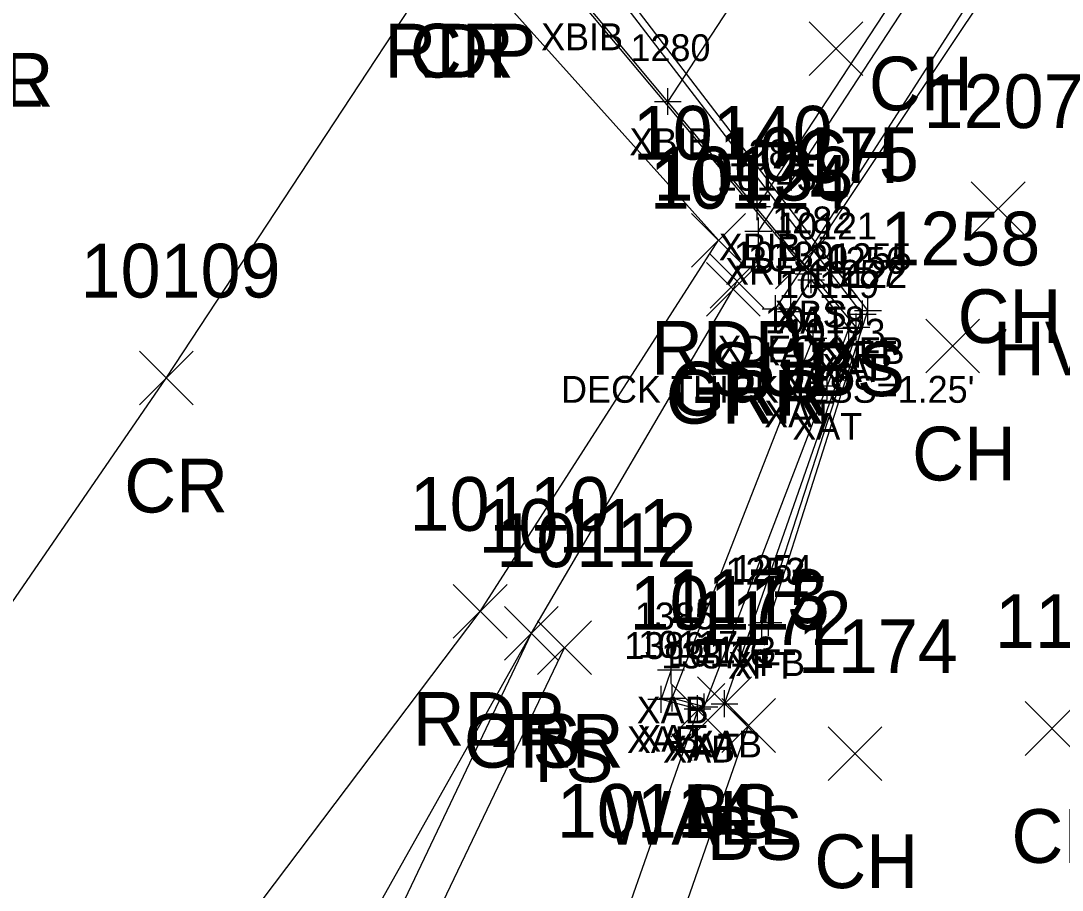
# Model space of a CAD drawing. Extents: x 1651685 to 1653558, y 889533 to 891085.
# Drawn here: x 1652681.1 to 1652719.83, y 890214.62 to 890246.97 of the extents above; entities that cross this region are included whole.
import ezdxf

# ---------------------------------------------------------------- set-up
doc = ezdxf.new("R2010")
doc.units = 0
for name, color, linetype in [('B_A', 7, 'Continuous'), ('B_C', 7, 'Continuous'), ('B_I', 7, 'Continuous'), ('B_TIC', 7, 'Continuous'), ('BB', 7, 'Continuous'), ('BELB', 7, 'Continuous'), ('BFT', 7, 'Continuous'), ('BR', 7, 'Continuous'), ('BSE', 7, 'Continuous'), ('BSUBM', 7, 'Continuous'), ('C_A', 7, 'Continuous'), ('L_A', 7, 'Continuous'), ('L_I', 7, 'Continuous'), ('L_TIC', 7, 'Continuous'), ('LELB', 7, 'Continuous'), ('LW', 7, 'Continuous'), ('P_A', 7, 'Continuous'), ('P_I', 7, 'Continuous'), ('P_TIC', 7, 'Continuous'), ('PET', 7, 'Continuous'), ('PRC', 7, 'Continuous'), ('R_A', 7, 'Continuous'), ('R_I', 7, 'Continuous'), ('R_TIC', 7, 'Continuous'), ('RGR', 7, 'Continuous'), ('U_A', 7, 'Continuous'), ('U_I', 7, 'Continuous'), ('U_TIC', 7, 'Continuous'), ('USA', 7, 'Continuous')]:
    doc.layers.add(name, color=color, linetype=linetype)

msp = doc.modelspace()

# ---------------------------------------------------------------- linework, layer by layer
at = {"layer": 'B_TIC'}
for p, q in [((1652705.17, 890243.967), (1652705.246, 890243.967)), ((1652708.492, 890240.052), (1652708.568, 890240.052)), ((1652708.538, 890239.146), (1652708.614, 890239.146)), ((1652710.404, 890237.557), (1652710.479, 890237.557)), ((1652710.5, 890237.331), (1652710.575, 890237.331)), ((1652709.175, 890236.253), (1652709.251, 890236.253)), ((1652709.747, 890236.148), (1652709.822, 890236.148)), ((1652712.414, 890236.055), (1652712.49, 890236.055)), ((1652712.613, 890236.191), (1652712.689, 890236.191)), ((1652712.179, 890235.573), (1652712.255, 890235.573)), ((1652710.58, 890235.155), (1652710.656, 890235.155)), ((1652711.907, 890235.524), (1652711.982, 890235.524)), ((1652710.049, 890233.837), (1652710.125, 890233.837)), ((1652711.096, 890233.378), (1652711.172, 890233.378)), ((1652711.096, 890233.378), (1652711.172, 890233.378)), ((1652708.661, 890224.484), (1652708.737, 890224.484)), ((1652708.916, 890224.583), (1652708.991, 890224.583)), ((1652705.29, 890222.819), (1652705.365, 890222.819)), ((1652704.926, 890221.718), (1652705.001, 890221.718)), ((1652705.33, 890221.765), (1652705.405, 890221.765)), ((1652706.273, 890221.367), (1652706.348, 890221.367)), ((1652706.527, 890221.439), (1652706.602, 890221.439)), ((1652706.527, 890221.439), (1652706.602, 890221.439)), ((1652707.276, 890221.555), (1652707.352, 890221.555))]:
    msp.add_line(p, q, dxfattribs=at)
for points in [[(1652705.167, 890243.467), (1652705.167, 890244.467)], [(1652704.667, 890243.967), (1652705.667, 890243.967)], [(1652708.489, 890239.552), (1652708.489, 890240.552)], [(1652707.989, 890240.052), (1652708.989, 890240.052)], [(1652708.535, 890238.646), (1652708.535, 890239.646)], [(1652708.035, 890239.146), (1652709.035, 890239.146)], [(1652710.4, 890237.057), (1652710.4, 890238.057)], [(1652709.9, 890237.557), (1652710.9, 890237.557)], [(1652710.496, 890236.831), (1652710.496, 890237.831)], [(1652709.996, 890237.331), (1652710.996, 890237.331)], [(1652709.172, 890235.753), (1652709.172, 890236.753)], [(1652709.743, 890235.648), (1652709.743, 890236.648)], [(1652712.411, 890235.555), (1652712.411, 890236.555)], [(1652712.61, 890235.691), (1652712.61, 890236.691)], [(1652708.672, 890236.253), (1652709.672, 890236.253)], [(1652709.243, 890236.148), (1652710.243, 890236.148)], [(1652711.903, 890235.024), (1652711.903, 890236.024)], [(1652711.911, 890236.055), (1652712.911, 890236.055)], [(1652712.11, 890236.191), (1652713.11, 890236.191)], [(1652712.176, 890235.073), (1652712.176, 890236.073)], [(1652710.577, 890234.655), (1652710.577, 890235.655)], [(1652711.676, 890235.573), (1652712.676, 890235.573)], [(1652710.077, 890235.155), (1652711.077, 890235.155)], [(1652711.403, 890235.524), (1652712.403, 890235.524)], [(1652710.046, 890233.337), (1652710.046, 890234.337)], [(1652709.546, 890233.837), (1652710.546, 890233.837)], [(1652711.093, 890232.878), (1652711.093, 890233.878)], [(1652711.093, 890232.878), (1652711.093, 890233.878)], [(1652710.593, 890233.378), (1652711.593, 890233.378)], [(1652710.593, 890233.378), (1652711.593, 890233.378)], [(1652708.912, 890224.083), (1652708.912, 890225.083)], [(1652708.658, 890223.984), (1652708.658, 890224.984)], [(1652708.158, 890224.484), (1652709.158, 890224.484)], [(1652708.412, 890224.583), (1652709.412, 890224.583)], [(1652705.286, 890222.319), (1652705.286, 890223.319)], [(1652704.786, 890222.819), (1652705.786, 890222.819)], [(1652704.922, 890221.218), (1652704.922, 890222.218)], [(1652705.326, 890221.265), (1652705.326, 890222.265)], [(1652707.273, 890221.055), (1652707.273, 890222.055)], [(1652704.422, 890221.718), (1652705.422, 890221.718)], [(1652704.826, 890221.765), (1652705.826, 890221.765)], [(1652706.269, 890220.867), (1652706.269, 890221.867)], [(1652706.523, 890220.939), (1652706.523, 890221.939)], [(1652706.523, 890220.939), (1652706.523, 890221.939)], [(1652705.769, 890221.367), (1652706.769, 890221.367)], [(1652706.023, 890221.439), (1652707.023, 890221.439)], [(1652706.023, 890221.439), (1652707.023, 890221.439)], [(1652706.773, 890221.555), (1652707.773, 890221.555)]]:
    msp.add_lwpolyline(points, dxfattribs=at)
at = {"layer": 'BB'}
for points in [[(1652718.204, 890263.952), (1652705.167, 890243.967)], [(1652721.557, 890259.987), (1652708.489, 890240.052)]]:
    msp.add_lwpolyline(points, dxfattribs=at)
at = {"layer": 'BELB'}
msp.add_lwpolyline([(1652709.172, 890236.253), (1652723.445, 890257.661), (1652723.976, 890257.346), (1652725.092, 890258.712), (1652723.412, 890260.555)], dxfattribs=at)
at = {"layer": 'BFT'}
for points in [[(1652708.912, 890224.583), (1652712.61, 890236.191), (1652701.636, 890250.529), (1652698.138, 890254.709), (1652696.627, 890256.861)], [(1652708.658, 890224.484), (1652712.411, 890236.055), (1652701.467, 890250.302), (1652696.763, 890256.497), (1652694.576, 890256.579)]]:
    msp.add_lwpolyline(points, dxfattribs=at)
at = {"layer": 'BR'}
msp.add_lwpolyline([(1652708.535, 890239.146), (1652722.284, 890260.183)], dxfattribs=at)
at = {"layer": 'BSE'}
msp.add_lwpolyline([(1652688.419, 890263.77), (1652698.151, 890252.192), (1652698.185, 890252.136), (1652710.4, 890237.557)], dxfattribs=at)
at = {"layer": 'BSUBM'}
for points in [[(1652707.273, 890221.555), (1652712.176, 890235.573), (1652700.432, 890249.63), (1652694.576, 890256.579), (1652684.615, 890268.453), (1652678.722, 890266.546)], [(1652706.523, 890221.439), (1652705.326, 890221.765), (1652710.046, 890233.837), (1652710.577, 890235.155), (1652709.743, 890236.148), (1652710.496, 890237.331), (1652711.903, 890235.524), (1652711.093, 890233.378)], [(1652706.523, 890221.439), (1652711.093, 890233.378)], [(1652705.286, 890222.819), (1652704.922, 890221.718), (1652706.269, 890221.367)]]:
    msp.add_lwpolyline(points, dxfattribs=at)
at = {"layer": 'L_TIC'}
for points in [[(1652710.419, 890244.933), (1652712.419, 890246.933)], [(1652712.419, 890244.933), (1652710.419, 890246.933)], [(1652716.454, 890238.976), (1652718.454, 890240.976)], [(1652718.454, 890238.976), (1652716.454, 890240.976)], [(1652714.763, 890233.863), (1652716.763, 890235.863)], [(1652716.763, 890233.863), (1652714.763, 890235.863)], [(1652699.091, 890223.174), (1652701.091, 890225.174)], [(1652701.091, 890223.174), (1652699.091, 890225.174)], [(1652700.322, 890222.637), (1652702.322, 890224.637)], [(1652702.322, 890222.637), (1652700.322, 890224.637)], [(1652706.273, 890220.555), (1652708.273, 890222.555)], [(1652708.273, 890220.555), (1652706.273, 890222.555)], [(1652705.281, 890220.305), (1652707.281, 890222.305)], [(1652707.281, 890220.305), (1652705.281, 890222.305)], [(1652707.172, 890219.743), (1652709.172, 890221.743)], [(1652709.172, 890219.743), (1652707.172, 890221.743)], [(1652718.459, 890219.631), (1652720.459, 890221.631)], [(1652720.459, 890219.631), (1652718.459, 890221.631)], [(1652711.128, 890218.692), (1652713.128, 890220.692)], [(1652713.128, 890218.692), (1652711.128, 890220.692)]]:
    msp.add_lwpolyline(points, dxfattribs=at)
at = {"layer": 'LELB'}
for points in [[(1652059.958, 889769.148), (1652077.097, 889776.338), (1652118.687, 889793.555), (1652148.832, 889805.136), (1652195.565, 889824.702), (1652235.22, 889839.021), (1652273.168, 889851.707), (1652312.186, 889868.505), (1652346.463, 889887.35), (1652384.438, 889904.888), (1652418.627, 889927.641), (1652449.257, 889948.785), (1652484.179, 889973.177), (1652505.899, 889994.659), (1652536.895, 890025.511), (1652566.282, 890055.689), (1652594.629, 890083.579), (1652622.175, 890122.044), (1652650.057, 890154.468), (1652669.869, 890181.835), (1652676.091, 890189.411), (1652687.771, 890202.227), (1652700.091, 890224.174)], [(1652693.386, 890207.032), (1652701.322, 890223.637)], [(1652711.469, 890174.982), (1652709.134, 890184.396), (1652705.235, 890200.05), (1652703.806, 890206.099), (1652704.13, 890209.141), (1652708.172, 890220.743), (1652707.273, 890221.555)]]:
    msp.add_lwpolyline(points, dxfattribs=at)
at = {"layer": 'LW'}
msp.add_lwpolyline([(1652703.573, 890213.567), (1652706.281, 890221.305)], dxfattribs=at)
at = {"layer": 'P_TIC'}
for points in [[(1652706.052, 890237.801), (1652708.052, 890239.801)], [(1652708.052, 890237.801), (1652706.052, 890239.801)], [(1652685.512, 890232.671), (1652687.512, 890234.671)], [(1652687.512, 890232.671), (1652685.512, 890234.671)], [(1652697.186, 890223.989), (1652699.186, 890225.989)], [(1652699.186, 890223.989), (1652697.186, 890225.989)]]:
    msp.add_lwpolyline(points, dxfattribs=at)
at = {"layer": 'PET'}
msp.add_lwpolyline([(1652310.071, 889873.858), (1652345.018, 889890.876), (1652381.133, 889910.269), (1652416.225, 889931.732), (1652447.247, 889952.285), (1652474.07, 889972.993), (1652503.702, 889997.944), (1652534.457, 890027.787), (1652563.385, 890057.924), (1652590.108, 890087.923), (1652620.326, 890123.876), (1652646.593, 890156.843), (1652667.225, 890184.01), (1652673.844, 890192.76), (1652698.186, 890224.989), (1652707.052, 890238.801), (1652697.139, 890249.857), (1652688.173, 890260.372)], dxfattribs=at)
at = {"layer": 'PRC'}
msp.add_lwpolyline([(1652339.131, 889902.361), (1652374.757, 889921.453), (1652409.696, 889942.759), (1652439.668, 889962.958), (1652466.375, 889983.158), (1652495.638, 890007.899), (1652525.652, 890036.364), (1652554.01, 890065.879), (1652580.922, 890096.263), (1652611.449, 890132.238), (1652636.96, 890165.085), (1652656.957, 890191.595), (1652665.106, 890202.523), (1652686.512, 890233.671), (1652697.139, 890249.857)], dxfattribs=at)
at = {"layer": 'R_TIC'}
for points in [[(1652706.742, 890236.28), (1652708.742, 890238.28)], [(1652708.742, 890236.28), (1652706.742, 890238.28)], [(1652706.601, 890235.977), (1652708.601, 890237.977)], [(1652708.601, 890235.977), (1652706.601, 890237.977)], [(1652699.091, 890223.174), (1652701.091, 890225.174)], [(1652701.091, 890223.174), (1652699.091, 890225.174)]]:
    msp.add_lwpolyline(points, dxfattribs=at)
at = {"layer": 'RGR'}
msp.add_lwpolyline([(1652681.549, 890185.195), (1652688.877, 890200.577), (1652700.091, 890224.174), (1652707.601, 890236.977), (1652707.742, 890237.28)], dxfattribs=at)
at = {"layer": 'U_TIC'}
for points in [[(1652709.168, 890237), (1652711.168, 890239)], [(1652711.168, 890237), (1652709.168, 890239)]]:
    msp.add_lwpolyline(points, dxfattribs=at)
at = {"layer": 'USA'}
msp.add_lwpolyline([(1652723.048, 890258.093), (1652710.168, 890238)], dxfattribs=at)

# ---------------------------------------------------------------- texts
at = {"layer": 'B_A'}
for s, p in [('XBIB', (1652700.454, 890245.873)), ('XBIB', (1652703.738, 890241.967)), ('XBIB', (1652707.06, 890238.052)), ('XRF', (1652707.295, 890237.146)), ('XBS', (1652709.14, 890235.557)), ('XAT', (1652709.201, 890235.331)), ('XDECK', (1652707.014, 890234.253)), ('XFB', (1652711.37, 890234.191)), ('XAT', (1652708.448, 890234.148)), ('XFT', (1652711.155, 890234.055)), ('XAT', (1652710.608, 890233.524)), ('XAB', (1652710.896, 890233.573)), ('XAT', (1652709.281, 890233.155)), ('XAT', (1652708.751, 890231.837)), ('XAT', (1652709.797, 890231.378)), ('XAT', (1652709.797, 890231.378)), ('XFB', (1652707.672, 890222.583)), ('XFT', (1652707.402, 890222.484)), ('XAB', (1652704.007, 890220.819)), ('XAB', (1652703.643, 890219.718)), ('XAT', (1652704.031, 890219.765)), ('XAT', (1652705.228, 890219.439)), ('XAT', (1652705.228, 890219.439)), ('XAB', (1652705.993, 890219.555)), ('XAB', (1652704.99, 890219.367))]:
    msp.add_text(s, height=1, dxfattribs=at).set_placement(p)
at = {"layer": 'B_C'}
msp.add_text("DECK THICKNESS=1.25'", height=1, dxfattribs=at).set_placement((1652701.196, 890232.753))
at = {"layer": 'B_I'}
for s, p in [('1280', (1652703.777, 890245.467)), ('1281', (1652707.426, 890241.552)), ('10145', (1652706.984, 890240.646)), ('1282', (1652709.054, 890239.057)), ('10121', (1652709.229, 890238.831)), ('10139', (1652707.617, 890237.753)), ('10120', (1652708.149, 890237.648)), ('1255', (1652711.264, 890237.691)), ('1256', (1652711.037, 890237.555)), ('10122', (1652710.352, 890237.024)), ('1257', (1652710.829, 890237.073)), ('10119', (1652709.305, 890236.655)), ('10118', (1652708.778, 890235.337)), ('10123', (1652709.542, 890234.878)), ('10123', (1652709.542, 890234.878)), ('1254', (1652707.566, 890226.083)), ('1253', (1652707.311, 890225.984)), ('1385', (1652703.94, 890224.319)), ('1386', (1652703.548, 890223.218)), ('10117', (1652704.059, 890223.265)), ('10116', (1652705.228, 890222.939)), ('10116', (1652705.228, 890222.939)), ('1173', (1652706.21, 890223.055)), ('1387', (1652704.923, 890222.867))]:
    msp.add_text(s, height=1, dxfattribs=at).set_placement(p)
at = {"layer": 'C_A'}
msp.add_text('HVCTRL', height=2, dxfattribs=at).set_placement((1652717.256, 890233.774))
at = {"layer": 'L_A'}
for s, p in [('CH', (1652712.644, 890243.634)), ('CH', (1652709.908, 890240.933)), ('CH', (1652715.942, 890234.976)), ('CH', (1652714.252, 890229.863)), ('TS', (1652698.5, 890219.174)), ('TS', (1652699.731, 890218.637)), ('BS', (1652705.714, 890216.555)), ('WALL', (1652702.77, 890216.305)), ('BS', (1652706.613, 890215.743)), ('CH', (1652717.948, 890215.631)), ('CH', (1652710.616, 890214.692))]:
    msp.add_text(s, height=2, dxfattribs=at).set_placement(p)
at = {"layer": 'L_I'}
for s, p in [('1207', (1652714.682, 890242.976)), ('1258', (1652713.071, 890237.863)), ('10111', (1652698.123, 890227.174)), ('10112', (1652698.787, 890226.637)), ('10115', (1652703.746, 890224.305)), ('1173', (1652705.147, 890224.555)), ('1172', (1652706.046, 890223.743)), ('1175', (1652717.334, 890223.631)), ('1174', (1652710.002, 890222.692)), ('10114', (1652701.038, 890216.567)), ('10114', (1652701.038, 890216.567))]:
    msp.add_text(s, height=2, dxfattribs=at).set_placement(p)
at = {"layer": 'P_A'}
for s, p in [('RDP', (1652694.627, 890244.857)), ('CR', (1652695.572, 890244.857)), ('RDP', (1652704.54, 890233.801)), ('CR', (1652684.945, 890228.671)), ('RDP', (1652695.674, 890219.989))]:
    msp.add_text(s, height=2, dxfattribs=at).set_placement(p)
at = {"layer": 'P_I'}
for s, p in [('10140', (1652703.863, 890241.801)), ('10109', (1652683.324, 890236.671)), ('10110', (1652695.564, 890227.989))]:
    msp.add_text(s, height=2, dxfattribs=at).set_placement(p)
at = {"layer": 'R_A'}
for s, p in [('GRR', (1652676.373, 890243.772)), ('GRL', (1652676.428, 890243.772)), ('GRR', (1652705.089, 890231.977)), ('GRR', (1652705.23, 890232.28)), ('GRR', (1652697.579, 890219.174))]:
    msp.add_text(s, height=2, dxfattribs=at).set_placement(p)
at = {"layer": 'R_I'}
for s, p in [('10138', (1652704.64, 890240.28)), ('10124', (1652704.499, 890239.977)), ('10111', (1652698.123, 890227.174))]:
    msp.add_text(s, height=2, dxfattribs=at).set_placement(p)
at = {"layer": 'U_A'}
msp.add_text('SUBS', height=2, dxfattribs=at).set_placement((1652706.704, 890233))
at = {"layer": 'U_I'}
msp.add_text('10175', height=2, dxfattribs=at).set_placement((1652707.066, 890241))

doc.saveas('drawing.dxf')
